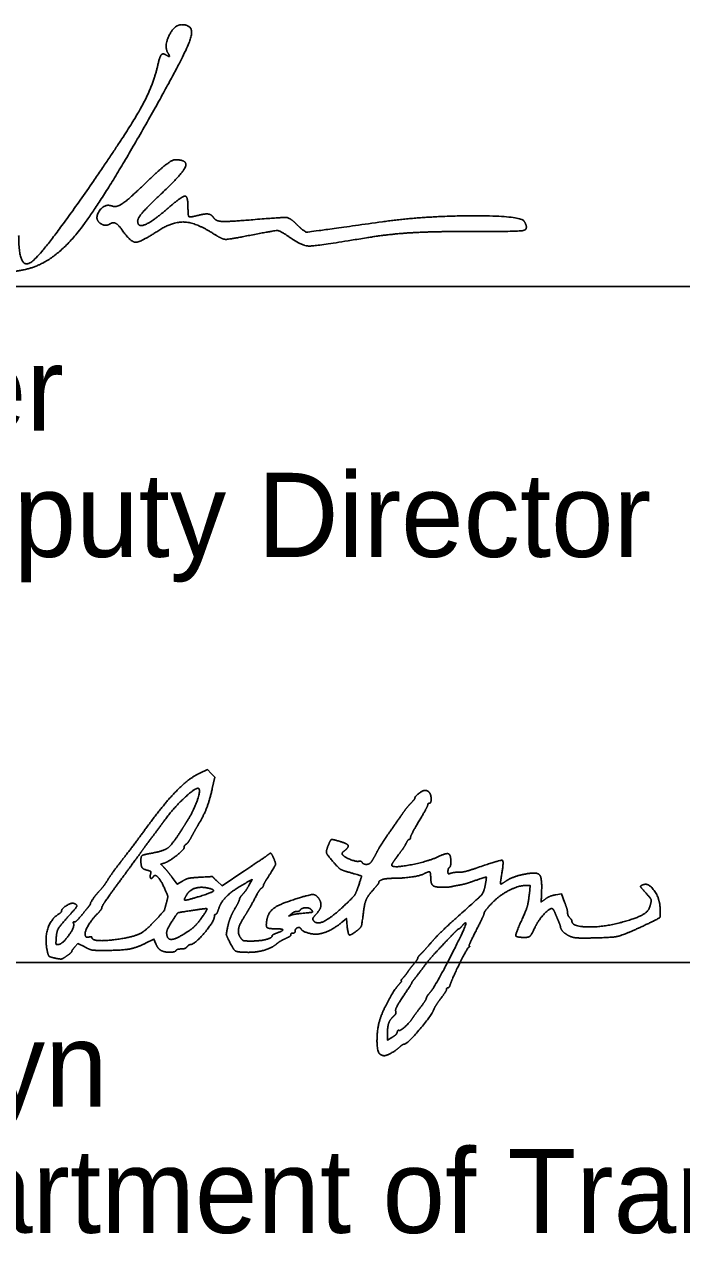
# Model space of a CAD drawing. Extents: x 0 to 34, y 0 to 22.
# Drawn here: x 25.694 to 26.787, y 6.834 to 8.887 of the extents above; entities that cross this region are included whole.
import ezdxf

# ---------------------------------------------------------------- set-up
doc = ezdxf.new("R2010")
doc.units = 0
doc.layers.add('SH_Data', color=7, linetype='Continuous')
doc.layers.add('SH_Text', color=7, linetype='Continuous')

msp = doc.modelspace()

# ---------------------------------------------------------------- linework, layer by layer
at = {"layer": 'SH_Data'}
for p, q in [((24.5, 8.451), (28, 8.451)), ((24.5, 7.326), (28, 7.326))]:
    msp.add_line(p, q, dxfattribs=at)
at = {"layer": 'SH_Text'}
for points in [[(25.9853, 7.6412), (25.9979, 7.6471), (26.0042, 7.6407), (26.0106, 7.6343), (26.0062, 7.6156)], [(25.9253, 7.4912), (25.9203, 7.4897), (25.9255, 7.4845)], [(26.0143, 7.4615), (26.0224, 7.4539), (26.0587, 7.478)], [(25.9392, 7.4678), (25.9477, 7.4563), (25.9565, 7.4615)], [(26.0682, 7.4563), (26.0726, 7.4642), (26.0671, 7.4613)], [(26.534, 7.4404), (26.5355, 7.4542), (26.5277, 7.4542)], [(26.5779, 7.4387), (26.5876, 7.4403), (26.5926, 7.4267)], [(26.23, 7.3926), (26.2293, 7.3994), (26.2234, 7.3943)], [(25.7937, 7.3519), (25.7822, 7.3577), (25.7771, 7.3519)], [(25.9123, 7.357), (25.909, 7.365), (25.8951, 7.3582)], [(26.2977, 7.2065), (26.2977, 7.1971), (26.3052, 7.2014)]]:
    msp.add_lwpolyline(points, dxfattribs=at)
for points in [[(25.9001, 8.7289), (25.9599, 8.8348), (25.9782, 8.8868), (25.9555, 8.8868)], [(25.9555, 8.8868), (25.943, 8.8868), (25.9255, 8.8507), (25.9325, 8.8393)], [(25.929, 8.8364), (25.9237, 8.8397), (25.9186, 8.8335), (25.9157, 8.8204)], [(25.9325, 8.8393), (25.9354, 8.8345), (25.934, 8.8333), (25.929, 8.8364)], [(25.9157, 8.8204), (25.9079, 8.7853), (25.8676, 8.7126), (25.8083, 8.6265)], [(25.6968, 8.4799), (25.7406, 8.4902), (25.8204, 8.588), (25.9001, 8.7289)], [(25.9441, 8.662), (25.9393, 8.662), (25.9163, 8.6437), (25.8931, 8.6213)], [(25.9208, 8.605), (25.9566, 8.6386), (25.9662, 8.662), (25.9441, 8.662)], [(25.8083, 8.6265), (25.7261, 8.5072), (25.6838, 8.4764), (25.6838, 8.5359)], [(25.8931, 8.6213), (25.8674, 8.5964), (25.8466, 8.5822), (25.8398, 8.5848)], [(25.8819, 8.5602), (25.8819, 8.5647), (25.8994, 8.5849), (25.9208, 8.605)], [(25.8398, 8.5848), (25.8266, 8.5899), (25.8091, 8.5627), (25.8209, 8.5554)], [(25.9657, 8.5812), (25.9657, 8.6018), (25.9555, 8.6015), (25.9309, 8.5801)], [(25.9309, 8.5801), (25.9067, 8.559), (25.8819, 8.549), (25.8819, 8.5602)], [(25.9843, 8.5698), (25.969, 8.566), (25.9657, 8.568), (25.9657, 8.5812)], [(26.0082, 8.5658), (26.0051, 8.5707), (25.9948, 8.5725), (25.9843, 8.5698)], [(26.0737, 8.5622), (26.0321, 8.5587), (26.0119, 8.5598), (26.0082, 8.5658)], [(26.1465, 8.5546), (26.136, 8.5651), (26.124, 8.5664), (26.0737, 8.5622)], [(26.5253, 8.5597), (26.5196, 8.569), (26.3577, 8.5684), (26.2895, 8.5588)], [(25.8209, 8.5554), (25.8251, 8.5528), (25.8322, 8.5529), (25.8368, 8.5557)], [(25.8368, 8.5557), (25.8413, 8.5585), (25.85, 8.5536), (25.8562, 8.5448)], [(25.8562, 8.5448), (25.8702, 8.5249), (25.8868, 8.5245), (25.9153, 8.5433)], [(25.9153, 8.5433), (25.9398, 8.5594), (25.9796, 8.5573), (26.0089, 8.5384)], [(26.0711, 8.5367), (26.1106, 8.5444), (26.1192, 8.544), (26.1344, 8.5334)], [(26.2895, 8.5588), (26.1676, 8.5417), (26.1597, 8.5414), (26.1465, 8.5546)], [(26.2628, 8.5321), (26.2984, 8.538), (26.3693, 8.5426), (26.4202, 8.5425)], [(26.4202, 8.5425), (26.5116, 8.5422), (26.5339, 8.5458), (26.5253, 8.5597)], [(26.0089, 8.5384), (26.0226, 8.5296), (26.0335, 8.5293), (26.0711, 8.5367)], [(26.1344, 8.5334), (26.1557, 8.5184), (26.1788, 8.5182), (26.2628, 8.5321)], [(25.6659, 8.498), (25.6743, 8.4779), (25.6783, 8.4756), (25.6968, 8.4799)], [(25.8957, 7.5493), (25.9254, 7.5899), (25.9672, 7.6328), (25.9853, 7.6412)], [(25.9838, 7.6154), (25.9802, 7.6191), (25.9416, 7.5833), (25.9262, 7.562)], [(25.9655, 7.5634), (25.9749, 7.5782), (25.9869, 7.6123), (25.9838, 7.6154)], [(26.0062, 7.6156), (26.0012, 7.5945), (25.992, 7.5709), (25.9826, 7.555)], [(26.3367, 7.5912), (26.3403, 7.5948), (26.3433, 7.5985), (26.3433, 7.5993)], [(26.3433, 7.5993), (26.3433, 7.6021), (26.3565, 7.6124), (26.3602, 7.6125)], [(26.3602, 7.6125), (26.3623, 7.6125), (26.3652, 7.6113), (26.3668, 7.6097)], [(26.3668, 7.6097), (26.3703, 7.6062), (26.3707, 7.591), (26.3673, 7.591)], [(26.3229, 7.574), (26.3269, 7.5798), (26.3331, 7.5875), (26.3367, 7.5912)], [(26.3649, 7.5884), (26.3649, 7.5871), (26.3584, 7.575), (26.3505, 7.5616)], [(26.3673, 7.591), (26.366, 7.591), (26.3649, 7.5898), (26.3649, 7.5884)], [(25.9262, 7.562), (25.9226, 7.5571), (25.9132, 7.5444), (25.9053, 7.5339)], [(25.955, 7.5467), (25.9583, 7.5519), (25.963, 7.5594), (25.9655, 7.5634)], [(26.3013, 7.543), (26.3092, 7.5542), (26.319, 7.5681), (26.3229, 7.574)], [(26.3505, 7.5616), (26.3426, 7.5482), (26.3361, 7.5358), (26.3361, 7.5341)], [(25.8555, 7.4959), (25.8644, 7.5072), (25.8825, 7.5313), (25.8957, 7.5493)], [(25.9052, 7.508), (25.9258, 7.5118), (25.9398, 7.5227), (25.955, 7.5467)], [(25.971, 7.5346), (25.9682, 7.5293), (25.9644, 7.5241), (25.9626, 7.523)], [(25.9826, 7.555), (25.9791, 7.549), (25.9739, 7.5398), (25.971, 7.5346)], [(26.2799, 7.5094), (26.2837, 7.5166), (26.2933, 7.5317), (26.3013, 7.543)], [(25.9053, 7.5339), (25.8974, 7.5234), (25.8893, 7.5124), (25.8873, 7.5095)], [(25.9593, 7.5176), (25.9593, 7.5139), (25.9335, 7.4938), (25.9253, 7.4912)], [(25.9626, 7.523), (25.9608, 7.522), (25.9593, 7.5195), (25.9593, 7.5176)], [(26.209, 7.4918), (26.1975, 7.5048), (26.1953, 7.5116), (26.1992, 7.5212)], [(26.1992, 7.5212), (26.203, 7.5303), (26.2061, 7.5313), (26.2188, 7.5275)], [(26.2188, 7.5275), (26.2308, 7.524), (26.2337, 7.5178), (26.226, 7.512)], [(26.3288, 7.5244), (26.3271, 7.5207), (26.3209, 7.5116), (26.3152, 7.5042)], [(26.3341, 7.531), (26.333, 7.531), (26.3306, 7.528), (26.3288, 7.5244)], [(26.3361, 7.5341), (26.3361, 7.5324), (26.3352, 7.531), (26.3341, 7.531)], [(25.834, 7.4665), (25.837, 7.4713), (25.8467, 7.4845), (25.8555, 7.4959)], [(25.8873, 7.5095), (25.8853, 7.5065), (25.87, 7.4856), (25.8532, 7.4629)], [(25.8873, 7.4959), (25.8873, 7.5028), (25.8914, 7.5055), (25.9052, 7.508)], [(25.8983, 7.4795), (25.8911, 7.4813), (25.8873, 7.487), (25.8873, 7.4959)], [(26.0587, 7.478), (26.0786, 7.4913), (26.0962, 7.5032), (26.0978, 7.5045)], [(26.0978, 7.5045), (26.1023, 7.5083), (26.1047, 7.5074), (26.1077, 7.5008)], [(26.1077, 7.5008), (26.1121, 7.4912), (26.1111, 7.4871), (26.1009, 7.4712)], [(26.226, 7.512), (26.2233, 7.5099), (26.2218, 7.507), (26.2228, 7.5057)], [(26.2228, 7.5057), (26.2254, 7.5019), (26.2453, 7.4937), (26.25, 7.4945)], [(26.25, 7.4945), (26.2522, 7.4949), (26.2548, 7.4941), (26.2556, 7.4927)], [(26.2706, 7.4932), (26.2719, 7.4948), (26.2761, 7.5021), (26.2799, 7.5094)], [(26.3152, 7.5042), (26.3096, 7.4967), (26.3049, 7.4894), (26.3049, 7.4881)], [(26.3049, 7.4881), (26.3049, 7.4828), (26.3645, 7.4938), (26.3825, 7.5023)], [(26.3825, 7.5023), (26.3955, 7.5085), (26.4033, 7.5054), (26.4033, 7.494)], [(26.4033, 7.494), (26.4033, 7.4894), (26.4022, 7.485), (26.4009, 7.4842)], [(26.4456, 7.4832), (26.486, 7.4971), (26.4919, 7.4955), (26.4878, 7.4716)], [(25.9034, 7.4732), (25.9043, 7.4768), (25.9031, 7.4783), (25.8983, 7.4795)], [(25.9077, 7.4685), (25.9052, 7.4646), (25.902, 7.4681), (25.9034, 7.4732)], [(25.9255, 7.4845), (25.9283, 7.4817), (25.9345, 7.4742), (25.9392, 7.4678)], [(26.2325, 7.4766), (26.2217, 7.4798), (26.2168, 7.4829), (26.209, 7.4918)], [(26.2493, 7.4529), (26.255, 7.4697), (26.2546, 7.4703), (26.2325, 7.4766)], [(26.2556, 7.4927), (26.2578, 7.4892), (26.2678, 7.4895), (26.2706, 7.4932)], [(26.3583, 7.4735), (26.3527, 7.4705), (26.3225, 7.4662), (26.3075, 7.4662)], [(26.3697, 7.4688), (26.3697, 7.4761), (26.366, 7.4777), (26.3583, 7.4735)], [(26.4009, 7.4842), (26.3996, 7.4833), (26.3985, 7.4805), (26.3985, 7.4779)], [(26.3985, 7.4779), (26.3985, 7.4739), (26.3995, 7.4734), (26.4039, 7.4748)], [(26.4039, 7.4748), (26.4069, 7.4757), (26.4127, 7.4764), (26.4168, 7.4762)], [(26.4168, 7.4762), (26.421, 7.476), (26.4339, 7.4792), (26.4456, 7.4832)], [(26.4938, 7.4608), (26.501, 7.4658), (26.5192, 7.4721), (26.5329, 7.4743)], [(26.5329, 7.4743), (26.5476, 7.4766), (26.5552, 7.4662), (26.5544, 7.4449)], [(25.8177, 7.4446), (25.8243, 7.452), (25.8285, 7.4577), (25.834, 7.4665)], [(25.8532, 7.4629), (25.8364, 7.4403), (25.8226, 7.4201), (25.8225, 7.4182)], [(25.9265, 7.4499), (25.9203, 7.4636), (25.9106, 7.4732), (25.9077, 7.4685)], [(25.9565, 7.4615), (25.963, 7.4654), (25.9706, 7.4671), (25.9857, 7.468)], [(25.9857, 7.468), (26.006, 7.4691), (26.0062, 7.4691), (26.0143, 7.4615)], [(26.0671, 7.4613), (26.0437, 7.4487), (26.021, 7.4281), (26.0168, 7.4156)], [(26.0554, 7.4381), (26.0608, 7.4441), (26.0633, 7.4477), (26.0682, 7.4563)], [(26.0913, 7.4544), (26.0913, 7.4533), (26.0897, 7.451), (26.0877, 7.4494)], [(26.1009, 7.4712), (26.0956, 7.4631), (26.0913, 7.4555), (26.0913, 7.4544)], [(26.231, 7.4256), (26.2414, 7.4356), (26.2455, 7.4418), (26.2493, 7.4529)], [(26.2833, 7.459), (26.2833, 7.4581), (26.2791, 7.4527), (26.2739, 7.4469)], [(26.3075, 7.4662), (26.296, 7.4662), (26.2833, 7.4624), (26.2833, 7.459)], [(26.389, 7.4512), (26.3766, 7.4512), (26.3697, 7.4575), (26.3697, 7.4688)], [(26.4057, 7.4526), (26.4024, 7.4518), (26.3949, 7.4512), (26.389, 7.4512)], [(26.4189, 7.4552), (26.4149, 7.4545), (26.409, 7.4534), (26.4057, 7.4526)], [(26.4161, 7.4036), (26.4516, 7.4352), (26.4585, 7.4434), (26.4609, 7.4566)], [(26.4403, 7.4613), (26.4325, 7.4586), (26.4229, 7.4558), (26.4189, 7.4552)], [(26.4609, 7.4566), (26.463, 7.4681), (26.4613, 7.4685), (26.4403, 7.4613)], [(26.5277, 7.4542), (26.515, 7.4542), (26.4812, 7.4357), (26.4691, 7.4222)], [(26.4878, 7.4716), (26.4865, 7.464), (26.4857, 7.4574), (26.4862, 7.4569)], [(26.4862, 7.4569), (26.4867, 7.4564), (26.4901, 7.4582), (26.4938, 7.4608)], [(26.7245, 7.4455), (26.7192, 7.4512), (26.719, 7.4539), (26.7236, 7.4556)], [(26.7236, 7.4556), (26.7322, 7.4589), (26.7506, 7.434), (26.7516, 7.4177)], [(25.8033, 7.4242), (25.8033, 7.4258), (25.8124, 7.4388), (25.8177, 7.4446)], [(25.9298, 7.4254), (25.9323, 7.4352), (25.932, 7.4374), (25.9265, 7.4499)], [(25.9649, 7.4407), (25.9579, 7.43), (25.9625, 7.4292), (25.9869, 7.4367)], [(25.9975, 7.4502), (25.9866, 7.4524), (25.9693, 7.4473), (25.9649, 7.4407)], [(25.9869, 7.4367), (26.0061, 7.4426), (26.0101, 7.4477), (25.9975, 7.4502)], [(26.0514, 7.4311), (26.0517, 7.4329), (26.0535, 7.436), (26.0554, 7.4381)], [(26.0809, 7.4401), (26.0727, 7.4247), (26.0649, 7.4109), (26.0588, 7.4012)], [(26.0877, 7.4494), (26.0858, 7.4478), (26.0827, 7.4436), (26.0809, 7.4401)], [(26.1347, 7.4284), (26.1665, 7.439), (26.1799, 7.4394), (26.185, 7.43)], [(26.2739, 7.4469), (26.2655, 7.4375), (26.2597, 7.4249), (26.2581, 7.4122)], [(26.5194, 7.3925), (26.5284, 7.4124), (26.5324, 7.4256), (26.534, 7.4404)], [(26.5544, 7.4449), (26.5537, 7.4265), (26.5536, 7.4268), (26.5613, 7.4323)], [(26.5613, 7.4323), (26.5651, 7.435), (26.5726, 7.4379), (26.5779, 7.4387)], [(26.7336, 7.4164), (26.7376, 7.4282), (26.736, 7.4331), (26.7245, 7.4455)], [(25.7506, 7.4068), (25.7532, 7.4084), (25.7553, 7.4108), (25.7553, 7.4121)], [(25.7553, 7.4121), (25.7554, 7.4159), (25.7721, 7.4259), (25.7759, 7.4244)], [(25.7759, 7.4244), (25.7819, 7.4221), (25.7796, 7.4172), (25.7653, 7.4013)], [(25.7888, 7.405), (25.7941, 7.4116), (25.7996, 7.4183), (25.8009, 7.4199)], [(25.8009, 7.4199), (25.8022, 7.4214), (25.8033, 7.4234), (25.8033, 7.4242)], [(25.8225, 7.4182), (25.8224, 7.4162), (25.8191, 7.4114), (25.8151, 7.4074)], [(25.9101, 7.3949), (25.9262, 7.4124), (25.9265, 7.413), (25.9298, 7.4254)], [(25.9677, 7.4119), (25.9499, 7.4093), (25.9479, 7.4082), (25.9406, 7.397)], [(25.9851, 7.4146), (25.9795, 7.4137), (25.9717, 7.4125), (25.9677, 7.4119)], [(25.9901, 7.4029), (25.9979, 7.4143), (25.997, 7.4164), (25.9851, 7.4146)], [(26.0168, 7.4156), (26.0151, 7.4104), (26.0128, 7.4062), (26.0117, 7.4062)], [(26.032, 7.3862), (26.0336, 7.3939), (26.0385, 7.4064), (26.0429, 7.414)], [(26.0429, 7.414), (26.0473, 7.4217), (26.0512, 7.4294), (26.0514, 7.4311)], [(26.0971, 7.3973), (26.0992, 7.4086), (26.1154, 7.422), (26.1347, 7.4284)], [(26.1523, 7.4131), (26.1516, 7.4119), (26.1491, 7.411), (26.1468, 7.411)], [(26.1708, 7.4142), (26.168, 7.4175), (26.1546, 7.4168), (26.1523, 7.4131)], [(26.1549, 7.4078), (26.1716, 7.4093), (26.174, 7.4103), (26.1708, 7.4142)], [(26.174, 7.3967), (26.1793, 7.3881), (26.2061, 7.4016), (26.231, 7.4256)], [(26.185, 7.43), (26.1882, 7.4239), (26.1848, 7.4125), (26.1774, 7.4046)], [(26.2581, 7.4122), (26.2553, 7.3897), (26.2536, 7.3842), (26.2479, 7.3797)], [(26.4691, 7.4222), (26.4632, 7.4157), (26.4585, 7.4091), (26.4585, 7.4076)], [(26.5709, 7.4158), (26.5666, 7.4158), (26.5483, 7.3953), (26.5436, 7.3851)], [(26.5765, 7.4092), (26.575, 7.4128), (26.5725, 7.4158), (26.5709, 7.4158)], [(26.5926, 7.4267), (26.5954, 7.4193), (26.5977, 7.4111), (26.5977, 7.4086)], [(26.6847, 7.3922), (26.7084, 7.3984), (26.7314, 7.4098), (26.7336, 7.4164)], [(26.7516, 7.4177), (26.7526, 7.4024), (26.7499, 7.3993), (26.7265, 7.3883)], [(25.7304, 7.3505), (25.7275, 7.369), (25.7382, 7.3991), (25.7506, 7.4068)], [(25.7653, 7.4013), (25.7516, 7.3862), (25.7466, 7.376), (25.746, 7.3622)], [(25.7753, 7.3908), (25.7745, 7.3927), (25.7751, 7.394), (25.7765, 7.3937)], [(25.7765, 7.3937), (25.7779, 7.3933), (25.7834, 7.3984), (25.7888, 7.405)], [(25.8151, 7.4074), (25.8053, 7.3978), (25.7929, 7.3757), (25.7947, 7.371)], [(25.8536, 7.3655), (25.8763, 7.3692), (25.8959, 7.3794), (25.9101, 7.3949)], [(25.9406, 7.397), (25.9324, 7.3843), (25.9292, 7.3745), (25.9315, 7.3687)], [(25.9602, 7.3742), (25.9714, 7.3812), (25.9824, 7.3917), (25.9901, 7.4029)], [(26.0097, 7.4032), (26.0095, 7.3946), (25.9764, 7.3558), (25.9693, 7.3558)], [(26.0117, 7.4062), (26.0106, 7.4062), (26.0097, 7.4048), (26.0097, 7.4032)], [(26.0588, 7.4012), (26.0508, 7.3886), (26.0486, 7.3734), (26.0537, 7.3666)], [(26.1106, 7.3822), (26.0991, 7.3822), (26.0951, 7.3867), (26.0971, 7.3973)], [(26.138, 7.4072), (26.1334, 7.4034), (26.1334, 7.4034), (26.1381, 7.4051)], [(26.1468, 7.411), (26.1445, 7.411), (26.1405, 7.4092), (26.138, 7.4072)], [(26.1381, 7.4051), (26.1407, 7.406), (26.1483, 7.4072), (26.1549, 7.4078)], [(26.1774, 7.4046), (26.1746, 7.4017), (26.1731, 7.3982), (26.174, 7.3967)], [(26.2234, 7.3943), (26.214, 7.3861), (26.194, 7.3755), (26.1849, 7.3738)], [(26.2479, 7.3797), (26.2362, 7.3705), (26.2318, 7.3736), (26.23, 7.3926)], [(26.3694, 7.2771), (26.3771, 7.2858), (26.4303, 7.3896), (26.4282, 7.3916)], [(26.372, 7.3609), (26.3792, 7.3693), (26.399, 7.3885), (26.4161, 7.4036)], [(26.4282, 7.3916), (26.4275, 7.3924), (26.4249, 7.3905), (26.4225, 7.3876)], [(26.4585, 7.4076), (26.4585, 7.406), (26.4525, 7.3932), (26.4453, 7.379)], [(26.5267, 7.3678), (26.5122, 7.3678), (26.5106, 7.3732), (26.5194, 7.3925)], [(26.5824, 7.395), (26.5806, 7.3992), (26.578, 7.4055), (26.5765, 7.4092)], [(26.5858, 7.3854), (26.5857, 7.3865), (26.5842, 7.3908), (26.5824, 7.395)], [(26.5977, 7.4086), (26.5977, 7.4061), (26.5993, 7.4025), (26.6013, 7.4005)], [(26.6013, 7.4005), (26.6033, 7.3985), (26.6049, 7.3958), (26.6049, 7.3945)], [(26.6049, 7.3945), (26.6049, 7.386), (26.6555, 7.3845), (26.6847, 7.3922)], [(25.7509, 7.3562), (25.7572, 7.3571), (25.7773, 7.3856), (25.7753, 7.3908)], [(25.7947, 7.371), (25.7956, 7.3686), (25.7979, 7.3677), (25.8009, 7.3685)], [(25.9315, 7.3687), (25.9335, 7.3634), (25.9471, 7.3661), (25.9602, 7.3742)], [(26.034, 7.3622), (26.0296, 7.3713), (26.0294, 7.3735), (26.032, 7.3862)], [(26.0713, 7.3618), (26.0853, 7.3618), (26.1057, 7.3669), (26.1057, 7.3704)], [(26.1057, 7.3704), (26.1057, 7.3714), (26.1094, 7.3736), (26.114, 7.3752)], [(26.114, 7.3752), (26.1243, 7.379), (26.1227, 7.3822), (26.1106, 7.3822)], [(26.1369, 7.3725), (26.1369, 7.3711), (26.1345, 7.3689), (26.1315, 7.3676)], [(26.1405, 7.375), (26.1385, 7.375), (26.1369, 7.3738), (26.1369, 7.3725)], [(26.1441, 7.3783), (26.1441, 7.3765), (26.1425, 7.375), (26.1405, 7.375)], [(26.1536, 7.3823), (26.1516, 7.3856), (26.1441, 7.3824), (26.1441, 7.3783)], [(26.1849, 7.3738), (26.1763, 7.3723), (26.1565, 7.3776), (26.1536, 7.3823)], [(26.4079, 7.3744), (26.4038, 7.3701), (26.3933, 7.359), (26.3845, 7.3497)], [(26.4167, 7.3822), (26.416, 7.3822), (26.412, 7.3786), (26.4079, 7.3744)], [(26.4225, 7.3876), (26.4201, 7.3846), (26.4175, 7.3822), (26.4167, 7.3822)], [(26.4453, 7.379), (26.438, 7.3649), (26.4329, 7.3533), (26.4339, 7.3533)], [(26.5436, 7.3851), (26.5379, 7.3727), (26.5331, 7.3678), (26.5267, 7.3678)], [(26.6014, 7.3698), (26.5944, 7.3732), (26.5859, 7.3816), (26.5858, 7.3854)], [(26.7265, 7.3883), (26.6917, 7.372), (26.6707, 7.3672), (26.6313, 7.3668)], [(25.747, 7.3328), (25.7361, 7.3348), (25.7323, 7.3389), (25.7304, 7.3505)], [(25.746, 7.3622), (25.7458, 7.3566), (25.7466, 7.3556), (25.7509, 7.3562)], [(25.7771, 7.3519), (25.7744, 7.3487), (25.7721, 7.3453), (25.7721, 7.3443)], [(25.8245, 7.3462), (25.8089, 7.3462), (25.803, 7.3473), (25.7937, 7.3519)], [(25.8009, 7.3685), (25.8035, 7.3691), (25.8057, 7.3688), (25.8057, 7.3677)], [(25.8057, 7.3677), (25.8057, 7.3631), (25.8313, 7.3619), (25.8536, 7.3655)], [(25.8951, 7.3582), (25.8796, 7.3504), (25.8544, 7.3462), (25.8245, 7.3462)], [(25.9205, 7.3463), (25.9179, 7.3478), (25.9142, 7.3526), (25.9123, 7.357)], [(25.9641, 7.3522), (25.9625, 7.3502), (25.9581, 7.3486), (25.9543, 7.3486)], [(25.9693, 7.3558), (25.9681, 7.3558), (25.9657, 7.3541), (25.9641, 7.3522)], [(26.0658, 7.343), (26.0483, 7.3431), (26.0413, 7.3474), (26.034, 7.3622)], [(26.0537, 7.3666), (26.0566, 7.3628), (26.0601, 7.3618), (26.0713, 7.3618)], [(26.1123, 7.3563), (26.1046, 7.3499), (26.0803, 7.343), (26.0658, 7.343)], [(26.1315, 7.3676), (26.1242, 7.3643), (26.1165, 7.3598), (26.1123, 7.3563)], [(26.3535, 7.3405), (26.3565, 7.3433), (26.3648, 7.3525), (26.372, 7.3609)], [(26.4331, 7.3515), (26.4304, 7.3497), (26.4052, 7.2987), (26.4022, 7.2892)], [(26.4339, 7.3533), (26.4349, 7.3533), (26.4345, 7.3525), (26.4331, 7.3515)], [(26.6313, 7.3668), (26.6164, 7.3666), (26.6061, 7.3677), (26.6014, 7.3698)], [(25.7637, 7.3369), (25.7572, 7.3324), (25.7536, 7.3315), (25.747, 7.3328)], [(25.7721, 7.3443), (25.7721, 7.3434), (25.7683, 7.34), (25.7637, 7.3369)], [(25.9461, 7.3462), (25.9441, 7.343), (25.9266, 7.3431), (25.9205, 7.3463)], [(25.9543, 7.3486), (25.9506, 7.3486), (25.9469, 7.3475), (25.9461, 7.3462)], [(26.3415, 7.3235), (26.3451, 7.3277), (26.3481, 7.3321), (26.3481, 7.3333)], [(26.3481, 7.3333), (26.3482, 7.3344), (26.3506, 7.3377), (26.3535, 7.3405)], [(26.3845, 7.3497), (26.3757, 7.3404), (26.3658, 7.3292), (26.3625, 7.3247)], [(26.3235, 7.3002), (26.3258, 7.3026), (26.3293, 7.3071), (26.3313, 7.3101)], [(26.3313, 7.3101), (26.3333, 7.3132), (26.3379, 7.3192), (26.3415, 7.3235)], [(26.3625, 7.3247), (26.3544, 7.3138), (26.3439, 7.3), (26.3409, 7.2965)], [(26.2875, 7.2378), (26.2934, 7.2526), (26.3105, 7.2825), (26.3176, 7.2904)], [(26.3176, 7.2904), (26.3203, 7.2933), (26.3218, 7.2958), (26.3209, 7.2958)], [(26.3209, 7.2958), (26.32, 7.2958), (26.3212, 7.2977), (26.3235, 7.3002)], [(26.3385, 7.2926), (26.3385, 7.292), (26.3322, 7.2821), (26.3244, 7.2705)], [(26.3409, 7.2965), (26.3396, 7.2949), (26.3385, 7.2931), (26.3385, 7.2926)], [(26.4022, 7.2892), (26.4013, 7.2862), (26.3996, 7.2838), (26.3983, 7.2838)], [(26.3244, 7.2705), (26.3158, 7.2574), (26.3108, 7.2477), (26.3115, 7.245)], [(26.3625, 7.2668), (26.3625, 7.2681), (26.3656, 7.2727), (26.3694, 7.2771)], [(26.3961, 7.2813), (26.3961, 7.2799), (26.3918, 7.2731), (26.3866, 7.2662)], [(26.3983, 7.2838), (26.3971, 7.2838), (26.3961, 7.2826), (26.3961, 7.2813)], [(26.3752, 7.2485), (26.3716, 7.2386), (26.3304, 7.1902), (26.3257, 7.1902)], [(26.3397, 7.2337), (26.341, 7.2358), (26.3467, 7.2436), (26.3523, 7.2509)], [(26.3523, 7.2509), (26.3579, 7.2583), (26.3625, 7.2654), (26.3625, 7.2668)], [(26.3866, 7.2662), (26.3814, 7.2593), (26.3763, 7.2513), (26.3752, 7.2485)], [(26.2857, 7.1733), (26.2798, 7.1771), (26.281, 7.2214), (26.2875, 7.2378)], [(26.3078, 7.2364), (26.3019, 7.2311), (26.2977, 7.2188), (26.2977, 7.2065)], [(26.3115, 7.245), (26.3122, 7.2424), (26.3106, 7.2388), (26.3078, 7.2364)], [(26.3169, 7.213), (26.3188, 7.2118), (26.3355, 7.2269), (26.3397, 7.2337)], [(26.3052, 7.2014), (26.3094, 7.2038), (26.3133, 7.2076), (26.3139, 7.2099)], [(26.3139, 7.2099), (26.3145, 7.2122), (26.3159, 7.2136), (26.3169, 7.213)], [(26.3183, 7.1856), (26.3121, 7.1799), (26.2961, 7.1709), (26.2922, 7.171)], [(26.3257, 7.1902), (26.3243, 7.1902), (26.321, 7.1881), (26.3183, 7.1856)], [(26.2922, 7.171), (26.2906, 7.171), (26.2877, 7.1721), (26.2857, 7.1733)]]:
    msp.add_open_spline(points, degree=2, dxfattribs=at)

# ---------------------------------------------------------------- texts
for s, p in [('Robert Weaver', (24.5, 8.211)), ('District       Deputy Director', (24.5, 8.001)), ('Pamela Boratyn', (24.5, 7.086)), ('Director, Department of Transportation', (24.5, 6.876))]:
    msp.add_text(s, height=0.14, dxfattribs=at).set_placement(p)

doc.saveas('drawing.dxf')
